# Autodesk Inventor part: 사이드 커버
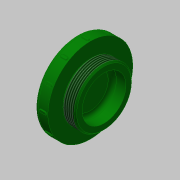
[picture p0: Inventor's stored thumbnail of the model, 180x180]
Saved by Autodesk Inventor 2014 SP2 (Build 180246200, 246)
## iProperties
Created: 2016-08
Part Number: 사이드 커버
Material: 스테인리스강
Document SubType Name: Modeling
Designer: mduedu
Density: 8.08 g/cm^3
Appearance: 진녹색
Author: mduedu
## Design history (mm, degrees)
sketch "스케치1"
  geometry: L1 (-5, 0)-(5, 0); L2 (-5, 0)-(-5, 31); L3 (-5, 31)-(5, 31); L4 (5, 31)-(5, 21); L5 (5, 21)-(15, 21); L6 (15, 21)-(15, 16); L7 (15, 16)-(5, 16); L8 (5, 16)-(5, 0); 2 further points
  constraints: 16 end point, 4 parallel, 2 perpendicular, 1 coincident, 1 collinear, 1 horizontal, 1 midpoint, 1 vertical
  dimensions: "d0" = 10 distance of L1.start L1.end; "d2" = 62 diameter of L3 L1; "d3" = 42 diameter of L5 L1; "d4" = 10 distance between parallel lines of L6 L8; "d5" = 5 distance of L5.end L6.end
revolve "회전1" sketch "스케치1" stored, may be unused: angle "d6" = 90 deg
fillet "모깎기1" dims "d7" = 3
sketch "스케치2"
  geometry: L1 (5, -31)-(5, 31) reference; L2 (5, 21)-(15, 21) reference; L3 (0, 0)-(5, 0); L4 (5, 21)-(6, 21); L5 (6, 21)-(6, 20); L6 (6, 20)-(5, 20); L7 (5, 20)-(5, 21)
  constraints: 10 end point, 2 parallel, 1 horizontal, 1 midpoint, 1 perpendicular
  dimensions: "d8" = 1 distance of L2.start L4.end; "d9" = 40 diameter of L6 L3
revolve "회전2" sketch "스케치2" stored, may be unused: angle "d10" = 90 deg
fillet "모깎기2" dims "d11" = 3
feature "스레드1" dims "d12" = 10, "d13" = 0
chamfer "모따기1" distance "d14" = 1; stored, may be unused: second distance "d15" = 2, angle "d16" = 45 deg
node "작업 평면1"
sketch "스케치3"
  geometry: L1 (1, -1)-(-4, -1); L2 (-4, -1)-(-4, 1); L3 (-4, 1)-(1, 1); L4 (1, 1)-(1, -1); 2 further points
  constraints: 8 end point, 2 parallel, 1 horizontal, 1 horizontal alignment, 1 midpoint, 1 perpendicular
  dimensions: "d18" = 2 distance of L3.end L1.start; "d20" = 5 distance of L1.start L1.end; "d21" = 1 distance from line of L4 point (0, 0)
extrude "돌출1" join sketch "스케치3" stored distance "d22" = 10; taper "d23" = 0 deg
fillet "모깎기3" dims "d24" = 1
fillet "모깎기4" dims "d25" = 0.2
sketch "스케치4"
  geometry: 2 further points
  constraints: 1 coincident, 1 other
feature "엠보싱1" sketch "스케치4" dims "d0" = 10, "d2" = 62, "d3" = 42, "d4" = 10, "d5" = 5, "d29" = 0.5, "d30" = 0
node "솔리드1"
pattern_circular "원형 패턴1" dims "d27" = 360 deg
other parameters: "d17" = 31.5
